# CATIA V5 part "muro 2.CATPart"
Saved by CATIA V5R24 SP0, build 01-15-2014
Part number: muro 2
Bounding box of the stored display mesh (mm): x 0 to 3, y -110 to 110, z -82.5 to 82.5
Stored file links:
  C:\Users\Fatec\Desktop\Maquina componentes catia\muro 2.CATPart
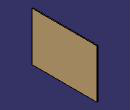
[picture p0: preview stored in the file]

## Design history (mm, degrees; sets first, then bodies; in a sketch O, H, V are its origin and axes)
Body1 (main body)
  Sketch1 on yz-plane, origin (0, 0, 0), H (0, 1, 0), V (0, 0, 1)
    line L1 (-110, 82.5) -> (110, 82.5)
    line L2 (110, 82.5) -> (110, -82.5)
    line L3 (110, -82.5) -> (-110, -82.5)
    line L4 (-110, -82.5) -> (-110, 82.5)
    length L3 = 220
    length L2 = 165
    horizontal: L1 H, L3 H
    vertical: L2 V, L4 V
    symmetry: L4 L2 V, L3 L1 H
  Pad1: profile Sketch1, direction (1, 0, 0), length 3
